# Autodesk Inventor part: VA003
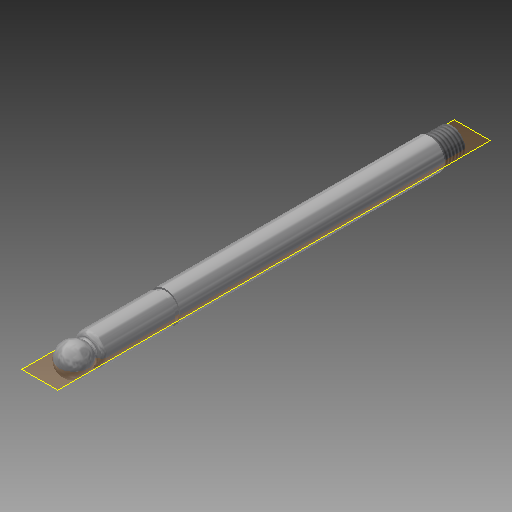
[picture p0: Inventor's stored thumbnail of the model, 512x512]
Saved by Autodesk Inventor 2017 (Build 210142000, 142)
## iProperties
Manager: P MOLLOY
Company: NUIG
Shininess: 64.0
Length Units: 11269
Angle Units: 11279
Time Units: 11290
Mass Units: 11283
Length Display Precision: 3
Angle Display Precision: 2
Compacted: True
Part Number: VA003
Document SubType Name: Modeling
Created: 2004-12
Designer: warren davies
Manufacturer: Standard
Standards Organization: Custom
Material: Non-Alloy Steel
Mass: 445.98 g
Surface Area: 133.995 cm^2
Volume: 56.8127 cm^3
Density: 7.85 g/cm^3
Appearance: Steel
Density: 0.0
Volumn: 0.0
Area: 0.0
PropertySet Name: Model Information
Control State: 0
Master: False
Checked Out: False
Title: SAFTY HANDLE
Subject: VICE ASSEMBLY
Author: warren davies
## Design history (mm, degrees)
sketch "Sketch1"
  geometry: C1 r 8 at (0, 0)
  constraints: 1 centre point
  dimensions: "d0" = 16 diameter of C1
extrude "Extrusion1" new body sketch "Sketch1" distance "d1" = 13; taper "d2" = 0 deg
sketch "Sketch2"
  geometry: C1 r 8 at (0, 0) reference; C2 r 9 at (0, 0)
  constraints: 1 centre point, 1 coincident
  dimensions: "d3" = 18 diameter of C2
extrude "Extrusion2" join sketch "Sketch2" distance "d4" = 156; taper "d5" = 0 deg
sketch "Sketch3"
  geometry: C1 r 9 at (0, 0) reference; C2 r 8 at (0, 0)
  constraints: 1 centre point, 1 coincident
  dimensions: "d6" = 16 diameter of C2
extrude "Extrusion3" join sketch "Sketch3" distance "d7" = 3; taper "d8" = 0 deg
sketch "Sketch4"
  geometry: C1 r 8 at (0, 0) reference; C2 r 9 at (0, 0)
  constraints: 1 centre point, 1 coincident
  dimensions: "d9" = 18 diameter of C2
extrude "Extrusion4" join sketch "Sketch4" distance "d10" = 43; taper "d11" = 0 deg
sketch "Sketch6"
  geometry: L1 (-9, 215)-(9, 215) reference; L2 (0, 215)-(0, 229.092); L3 (0, 215)-(0, 232); A1 r 9 centre (0, 223) between (4.123, 215) and (0, 232)
  constraints: 4 end point, 3 point on line, 2 point on circle, 1 centre point, 1 midpoint, 1 perpendicular
  dimensions: "d19" = 18 diameter of A1; "d20" = 8 distance from line of L1 A1.centre
revolve "Revolution2" sketch "Sketch6" stored, may be unused: angle "d21" = 90 deg
fillet "Fillet1" dims "d22" = 1
fillet "Fillet2" dims "d23" = 3
thread "Thread1" dims "d24" = 10, "d25" = 0
body "Solid1"
